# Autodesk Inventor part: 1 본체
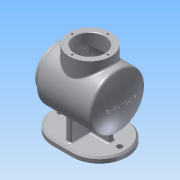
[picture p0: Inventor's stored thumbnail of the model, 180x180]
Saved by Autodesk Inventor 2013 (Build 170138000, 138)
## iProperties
Created: 2016-04
Part Number: 1 본체
Material: 알루미늄 6061
Document SubType Name: Modeling
Designer: Administrator
Mass: 911.528 g
Surface Area: 1226.33 cm^2
Volume: 336.357 cm^3
Density: 2.71 g/cm^3
Author: Administrator
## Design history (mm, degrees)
sketch "스케치1"
  geometry: L1 (-17.5, 50)-(17.5, 50); L2 (17.5, -50)-(-17.5, -50); A1 r 50 centre (17.5, 0) between (17.5, -50) and (17.5, 50); A2 r 50 centre (-17.5, 0) between (-17.5, 50) and (-17.5, -50); 2 further points
  constraints: 4 end point, 4 point on circle, 4 tangent, 2 centre point, 2 horizontal, 2 horizontal alignment, 1 midpoint, 1 vertical alignment
  dimensions: "d0" = 100 distance between parallel lines of L1 L2; "d2" = 135 dimension on A2 A1
extrude "돌출1" new body sketch "스케치1" distance "d3" = 10; taper "d4" = 0 deg
sketch "스케치3"
  geometry: L1 (67.5, 0)-(67.5, 10) reference; L2 (-67.5, 0)-(-67.5, 10) reference; L3 (-97.541, 79)-(111.394, 79); L4 (61.544, 79)-(61.544, 117); L5 (61.544, 117)-(49.544, 117); L6 (49.544, 117)-(49.544, 129); L7 (49.544, 129)-(-49.544, 129); A1 r 120 centre (59.544, 79) between (-49.544, 129) and (-60.456, 79); 2 further points
  constraints: 10 end point, 4 perpendicular, 3 point on line, 2 point on circle, 1 centre point, 1 midpoint, 1 parallel, 1 vertical alignment
  dimensions: "d19" = 79 vertical distance of L1.start L3.end; "d21" = 12 distance of L4.end L5.end; "d24" = 120 radius of A1; "d25" = 110 horizontal distance of L6.end A1.end; "d26" = 100 diameter of L7 L3; "d27" = 76 diameter of L5 L3
revolve "회전2" sketch "스케치3" stored, may be unused: angle "d28" = 90 deg
node "작업 평면1"
sketch "스케치9"
  geometry: C1 r 38 at (0, 0); 1 further point
  constraints: 1 centre point, 1 coincident
  dimensions: "d56" = 76 diameter of C1
extrude "돌출4" join sketch "스케치9" distance "d58" = 50; taper "d59" = 0 deg
sketch "스케치5"
  geometry: L1 (-49.544, 29)-(-49.544, 129) reference; L2 (49.544, 29)-(49.544, 129) reference; L3 (-17.5, 10)-(-67.5, 10) reference; L4 (67.5, 10)-(17.5, 10) reference; L5 (-29.773, 68)-(29.773, 68); L6 (29.773, 68)-(40, 10); L7 (-29.773, 68)-(-40, 10); L8 (17.5, 10)-(-17.5, 10) reference; 1 further point
  constraints: 6 end point, 2 point on line, 1 parallel
  dimensions: "d31" = 40 horizontal distance of point (0, 0) L6.end; "d32" = 80 distance of L6.end L7.end; "d33" = 100 deg angle of L4 L6; "d34" = 100 deg angle of L3 L7; "d35" = 58 distance between parallel lines of L4 L5
extrude "돌출2" join sketch "스케치5" stored distance "d36" = 10; taper "d37" = 0 deg
sketch "스케치7"
  geometry: L1 (50, 10)-(-50, 10) reference; L2 (-40, 49)-(-40, 10); L3 (-40, 49)-(40, 49); L4 (40, 49)-(40, 10); A1 r 50 centre (0, 79) between (-40, 49) and (40, 49) reference; 1 further point
  constraints: 6 end point, 3 perpendicular, 2 point on circle, 2 point on line
  dimensions: "d38" = 80 distance between parallel lines of L2 L4
extrude "돌출3" join sketch "스케치7" stored distance "d39" = 10; taper "d40" = 0 deg
node "작업 평면4"
sketch "스케치15"
  geometry: 2 further points
  constraints: 1 vertical alignment, 1 other
  dimensions: "d106" = 79 distance of point (0, 0) point (0, 79)
feature "엠보싱1" sketch "스케치15" dims "d107" = 0.5, "d108" = 0
sketch "스케치8"
  geometry: L1 (-49.544, 129)-(49.544, 129) reference; L2 (49.544, 117)-(61.544, 117) reference; L3 (61.544, 41)-(61.544, 117) reference; L4 (-46.286, 126)-(44.544, 126); L5 (46.544, 124)-(46.544, 79); L6 (61.544, 79)-(-60.456, 79); L7 (49.544, 29)-(49.544, 129) reference; A1 r 120 centre (59.544, 79) between (-49.544, 129) and (-49.544, 29) reference; A2 r 117 centre (59.544, 79) between (-48.127, 124.783) and (-57.456, 79); A3 r 2 centre (-46.286, 124) between (-46.286, 126) and (-48.127, 124.783); A4 r 2 centre (44.544, 124) between (46.544, 124) and (44.544, 126); 3 further points
  constraints: 8 point on circle, 6 end point, 5 point on line, 4 tangent, 3 centre point, 1 equal radius, 1 midpoint
  dimensions: "d41" = 3 radial gap between concentric circles of A1 A2; "d42" = 3 distance between parallel lines of L1 L4; "d44" = 3 distance between parallel lines of L7 L5; "d69" = 2 radius of A3
revolve "회전3" sketch "스케치8" stored, may be unused: angle "d45" = 90 deg
hole "구멍1" diameter "d48" = 54; stored, may be unused: countersink angle "d52" = 90 deg, drill point angle "d54" = 0 deg; dims "d46" = 10, "d47" = 10, "d49" = 6, "d50" = 4, "d51" = 2, "d53" = 20
hole "구멍2" diameter "d62" = 54; stored, may be unused: countersink angle "d66" = 90 deg, drill point angle "d68" = 0 deg; dims "d60" = 10, "d61" = 10, "d63" = 6, "d64" = 4, "d65" = 2, "d67" = 40
fillet "모깎기1" dims "d70" = 5
chamfer "모따기1" distance "d71" = 1; stored, may be unused: second distance "d72" = 2, angle "d73" = 45 deg
chamfer "모따기2" distance "d74" = 3; stored, may be unused: second distance "d75" = 2, angle "d76" = 45 deg
sketch "스케치10" dims "d77" = 65
  geometry: 3 further points
  constraints: 2 vertical alignment, 1 coincident, 2 other
hole "구멍3" sketch "스케치10" at (0, 32.5) diameter "d79" = 3.242; stored, may be unused: countersink angle "d83" = 90 deg, drill point angle "d85" = 118 deg; dims "d80" = 8, "d81" = 4, "d82" = 2, "d84" = 10
sketch "스케치11" dims "d89" = 65
  geometry: C1 r 38 at (0, 0) reference; 3 further points
  constraints: 2 vertical alignment, 1 coincident, 2 other
hole "구멍4" sketch "스케치11" at (0, 32.5) diameter "d91" = 3.242; stored, may be unused: countersink angle "d95" = 90 deg, drill point angle "d97" = 118 deg; dims "d92" = 8, "d93" = 4, "d94" = 2, "d96" = 10
fillet "모깎기2" dims "d102" = 3
fillet "모깎기3" dims "d103" = 3
fillet "모깎기4" dims "d109" = 3
sketch "스케치16"
  geometry: 3 further points
  constraints: 2 horizontal alignment
  dimensions: "d110" = 54 distance of point (54, 0) point (0, 0); "d111" = 54 distance of point (-54, 0) point (0, 0)
hole "구멍5" sketch "스케치16" at (-54, 0), (54, 0) diameter "d112" = 10; stored, may be unused: countersink angle "d116" = 90 deg, drill point angle "d118" = 118 deg; dims "d113" = 8, "d114" = 4, "d115" = 2, "d117" = 10
fillet "모깎기5" dims "d119" = 3
node "솔리드1"
pattern_circular "원형 패턴1" dims angle "d87" = 360 deg
pattern_circular "원형 패턴2" dims angle "d99" = 360 deg
other parameters: "d55" = 144, "d105" = 48
